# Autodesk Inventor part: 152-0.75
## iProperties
Created: 2007-06
Part Number: 152-0.75
Document SubType Name: Modeling
Designer: btaylor
Density: 1 g/cm^3
Author: btaylor
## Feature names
1. Sweep1
2. Extrusion1
3. Extrusion2
4. Fillet1
5. Fillet2
6. Extrusion3
7. Chamfer1
8. Fillet3
9. Chamfer2
10. Sweep2
11. Fillet4
12. Fillet5
